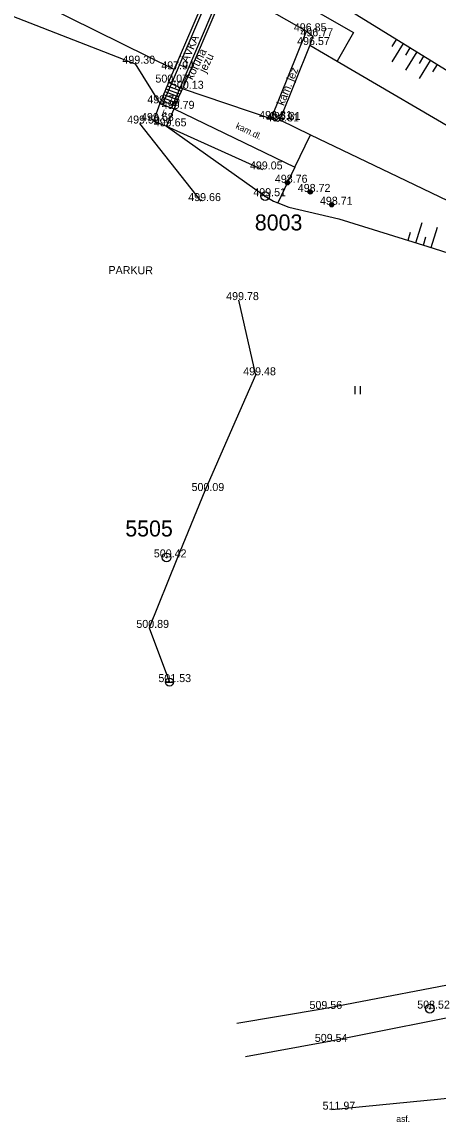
# Model space of a CAD drawing. Extents: x -668867 to -667827, y -1131943 to -1131019.
# Drawn here: x -668314 to -668275, y -1131724 to -1131620.9 of the extents above; entities that cross this region are included whole.
import ezdxf

# ---------------------------------------------------------------- set-up
doc = ezdxf.new("R2010")
doc.units = 0
for name, color, linetype in [('G_Bod_tecka', 7, 'Continuous'), ('G_Bod_vyska', 7, 'Continuous'), ('G_Bodove_pole', 7, 'Continuous'), ('G_Breh_Teren', 7, 'Continuous'), ('G_Budovy_Objekty', 7, 'Continuous'), ('G_Cesty_Schody', 7, 'Continuous'), ('G_Objekty-Studny', 7, 'Continuous'), ('G_Plochy_zpevnene', 7, 'Continuous'), ('G_Ploty', 7, 'Continuous'), ('G_Popisy_povrchu', 7, 'Continuous'), ('G_Poznamky_odkaz', 7, 'Continuous'), ('G_Site-Sloupy', 7, 'Continuous'), ('G_Vyskove_srafy', 7, 'Continuous'), ('G_Zabradli_Svodidla', 7, 'Continuous'), ('G_Zelen-okraj', 7, 'Continuous'), ('G_Zelen-rozhrani', 7, 'Continuous'), ('G_Zelen-Znacky', 7, 'Continuous')]:
    doc.layers.add(name, color=color, linetype=linetype)

msp = doc.modelspace()

# ---------------------------------------------------------------- linework, layer by layer
at = {"layer": 'G_Bod_tecka'}
for p, q in [((-668287.32, -1131621.79), (-668287.32, -1131621.79)), ((-668286.71, -1131622.26), (-668286.71, -1131622.26)), ((-668287.01, -1131623.08), (-668287.01, -1131623.08)), ((-668303.4, -1131624.83), (-668303.4, -1131624.83)), ((-668299.77, -1131625.36), (-668299.77, -1131625.36)), ((-668300.26, -1131626.6), (-668300.26, -1131626.6)), ((-668298.96, -1131627.18), (-668298.96, -1131627.18)), ((-668301.07, -1131628.55), (-668301.07, -1131628.55)), ((-668299.72, -1131629.06), (-668299.72, -1131629.06)), ((-668302.98, -1131630.44), (-668302.98, -1131630.44)), ((-668301.67, -1131630.2), (-668301.67, -1131630.2)), ((-668290.63, -1131630.01), (-668290.63, -1131630.01)), ((-668289.96, -1131630.24), (-668289.96, -1131630.24)), ((-668289.82, -1131630.1), (-668289.82, -1131630.1)), ((-668300.46, -1131630.7), (-668300.46, -1131630.7)), ((-668291.43, -1131634.74), (-668291.43, -1131634.74)), ((-668289.1, -1131635.99), (-668289.1, -1131635.99)), ((-668286.96, -1131636.85), (-668286.96, -1131636.85)), ((-668297.22, -1131637.71), (-668297.22, -1131637.71)), ((-668291.19, -1131637.25), (-668291.19, -1131637.25)), ((-668284.95, -1131638.05), (-668284.95, -1131638.05)), ((-668293.68, -1131646.99), (-668293.68, -1131646.99)), ((-668292.09, -1131654.04), (-668292.09, -1131654.04)), ((-668296.87, -1131664.89), (-668296.87, -1131664.89)), ((-668300.44, -1131671.11), (-668300.44, -1131671.11)), ((-668302.07, -1131677.72), (-668302.07, -1131677.72)), ((-668300.17, -1131682.8), (-668300.17, -1131682.8)), ((-668285.83, -1131713.44), (-668285.83, -1131713.44)), ((-668275.73, -1131713.41), (-668275.73, -1131713.41)), ((-668285.34, -1131716.53), (-668285.34, -1131716.53)), ((-668284.92, -1131722.88), (-668284.92, -1131722.88))]:
    msp.add_line(p, q, dxfattribs=at)
at = {"layer": 'G_Bodove_pole'}
for centre, radius in [((-668291.19, -1131637.25), 0.412), ((-668291.19, -1131637.25), 0.05), ((-668300.44, -1131671.11), 0.412), ((-668300.44, -1131671.11), 0.05), ((-668275.73, -1131713.41), 0.412), ((-668275.73, -1131713.41), 0.05)]:
    msp.add_circle(centre, radius, dxfattribs=at)
at = {"layer": 'G_Breh_Teren'}
for p, q in [((-668287.01, -1131623.08), (-668284.42, -1131624.59)), ((-668289.82, -1131630.1), (-668286.92, -1131631.49))]:
    msp.add_line(p, q, dxfattribs=at)
for points in [[(-668415.19, -1131594.85), (-668405.92, -1131594.75), (-668396.65, -1131594.66), (-668394.42, -1131594.69), (-668390.28, -1131595.04), (-668386.68, -1131595.6), (-668383.55, -1131596.28), (-668378.11, -1131597.76), (-668370.03, -1131600.44), (-668362.02, -1131603.26), (-668343.64, -1131609.6), (-668334.51, -1131612.86), (-668325.43, -1131616.28), (-668314.41, -1131620.56), (-668303.4, -1131624.83)], [(-668299.73, -1131625.37), (-668311.95, -1131619.35)], [(-668303.4, -1131624.83), (-668301.07, -1131628.55)], [(-668284.42, -1131624.59), (-668271.7, -1131632.04), (-668256.39, -1131640.99), (-668252.24, -1131643.3), (-668248.54, -1131645.17), (-668241.94, -1131648.18), (-668231.8, -1131652.31), (-668221.46, -1131656.34), (-668218.75, -1131657.34), (-668213.93, -1131658.81), (-668210.27, -1131659.7), (-668204.78, -1131660.72)], [(-668300.46, -1131630.7), (-668295.83, -1131633.98), (-668291.19, -1131637.25), (-668290.42, -1131637.71), (-668290.01, -1131637.87)], [(-668286.92, -1131631.49), (-668277.98, -1131635.78), (-668266.14, -1131641.46), (-668254.29, -1131647.41), (-668242.42, -1131653.43), (-668237.46, -1131655.76), (-668233.04, -1131657.64), (-668229.12, -1131659.17), (-668222.17, -1131661.58), (-668216.91, -1131663.18), (-668208.97, -1131665.24), (-668201.03, -1131666.92), (-668199.36, -1131667.09), (-668198.09, -1131667.04), (-668196.17, -1131666.72), (-668194.32, -1131666.1)], [(-668290.01, -1131637.87), (-668288.96, -1131638.28), (-668284.28, -1131639.36), (-668275.91, -1131641.96), (-668267.55, -1131644.62), (-668264.11, -1131645.93), (-668261.21, -1131647.32), (-668258.74, -1131648.68), (-668254.51, -1131651.29), (-668248.2, -1131655.36), (-668244.98, -1131657.3), (-668241.67, -1131659.07), (-668236.54, -1131661.51), (-668231.93, -1131663.55), (-668227.82, -1131665.21), (-668224.18, -1131666.55), (-668220.99, -1131667.61), (-668218.18, -1131668.43), (-668213.27, -1131669.62), (-668209.61, -1131670.26), (-668206.88, -1131670.59)], [(-668302.07, -1131677.72), (-668300.17, -1131682.8)]]:
    msp.add_lwpolyline(points, dxfattribs=at)
at = {"layer": 'G_Budovy_Objekty'}
for p, q in [((-668297.96, -1131621.25), (-668296.1, -1131616.94)), ((-668294.81, -1131617.51), (-668298.96, -1131627.18)), ((-668299.73, -1131625.37), (-668297.96, -1131621.25)), ((-668300.26, -1131626.6), (-668299.73, -1131625.37))]:
    msp.add_line(p, q, dxfattribs=at)
at = {"layer": 'G_Cesty_Schody'}
for p, q in [((-668287.32, -1131621.79), (-668286.71, -1131622.26)), ((-668286.71, -1131622.26), (-668287.01, -1131623.08)), ((-668289.96, -1131630.24), (-668290.63, -1131630.01)), ((-668289.82, -1131630.1), (-668289.96, -1131630.24))]:
    msp.add_line(p, q, dxfattribs=at)
for points in [[(-668300.61, -1131627.44), (-668300.73, -1131627.72)], [(-668300.5, -1131627.17), (-668300.61, -1131627.44)], [(-668300.61, -1131627.44), (-668299.28, -1131627.95)], [(-668300.38, -1131626.89), (-668300.5, -1131627.17)], [(-668300.5, -1131627.17), (-668299.16, -1131627.67)], [(-668300.26, -1131626.6), (-668300.38, -1131626.89)], [(-668300.38, -1131626.89), (-668299.05, -1131627.39)], [(-668298.96, -1131627.18), (-668300.26, -1131626.6)], [(-668299.16, -1131627.67), (-668299.05, -1131627.39)], [(-668299.05, -1131627.39), (-668298.96, -1131627.18)], [(-668300.96, -1131628.28), (-668301.07, -1131628.55)], [(-668301.07, -1131628.55), (-668299.72, -1131629.06)], [(-668300.84, -1131628), (-668300.96, -1131628.28)], [(-668300.96, -1131628.28), (-668299.61, -1131628.79)], [(-668300.73, -1131627.72), (-668300.84, -1131628)], [(-668300.84, -1131628), (-668299.5, -1131628.51)], [(-668300.73, -1131627.72), (-668299.39, -1131628.23)], [(-668299.61, -1131628.79), (-668299.5, -1131628.51)], [(-668299.5, -1131628.51), (-668299.39, -1131628.23)], [(-668299.39, -1131628.23), (-668299.28, -1131627.95)], [(-668299.28, -1131627.95), (-668299.16, -1131627.67)], [(-668299.72, -1131629.06), (-668299.61, -1131628.79)], [(-668293.86, -1131714.78), (-668285.83, -1131713.44), (-668270.48, -1131710.49), (-668262.65, -1131708.7), (-668254.82, -1131706.91), (-668251.21, -1131706.13), (-668245.77, -1131705.05), (-668240.35, -1131703.91), (-668234.27, -1131702.51), (-668228.2, -1131701.07), (-668225.41, -1131700.4), (-668222.63, -1131699.73), (-668217.07, -1131698.35), (-668211.52, -1131696.94), (-668207.58, -1131695.86)], [(-668206.76, -1131698.82), (-668210.49, -1131699.81), (-668219.14, -1131701.98), (-668227.81, -1131704.09), (-668233.92, -1131705.54), (-668240.04, -1131706.94), (-668247.27, -1131708.53), (-668254.5, -1131710.1), (-668261.74, -1131711.65), (-668268.98, -1131713.22), (-668269.64, -1131713.37), (-668270.29, -1131713.51), (-668285.34, -1131716.53), (-668293.02, -1131717.92)]]:
    msp.add_lwpolyline(points, dxfattribs=at)
at = {"layer": 'G_Objekty-Studny'}
msp.add_lwpolyline([(-668300.55, -1131682.8), (-668299.8, -1131682.8)], dxfattribs=at)
msp.add_circle((-668300.17, -1131682.8), 0.375, dxfattribs=at)
at = {"layer": 'G_Plochy_zpevnene'}
for points in [[(-668293.97, -1131615.57), (-668282.89, -1131621.91)], [(-668294.81, -1131617.51), (-668287.32, -1131621.79)], [(-668290.63, -1131630.01), (-668287.32, -1131621.79)], [(-668282.89, -1131621.91), (-668284.42, -1131624.59)], [(-668287.01, -1131623.08), (-668289.82, -1131630.1)], [(-668290.63, -1131630.01), (-668298.96, -1131627.18)], [(-668301.07, -1131628.55), (-668301.67, -1131630.2)], [(-668300.46, -1131630.7), (-668299.72, -1131629.06)], [(-668299.72, -1131629.06), (-668288.4, -1131634.54)], [(-668301.67, -1131630.2), (-668300.46, -1131630.7)], [(-668288.4, -1131634.54), (-668286.92, -1131631.49)], [(-668284.92, -1131722.88), (-668270.22, -1131721.43), (-668270.12, -1131721.42)]]:
    msp.add_lwpolyline(points, dxfattribs=at)
at = {"layer": 'G_Ploty'}
for p, q in [((-668264.03, -1131631.7), (-668292.33, -1131614.27)), ((-668302.98, -1131630.44), (-668297.22, -1131637.71)), ((-668293.68, -1131646.99), (-668292.09, -1131654.04))]:
    msp.add_line(p, q, dxfattribs=at)
at = {"layer": 'G_Site-Sloupy'}
for centre, radius in [((-668289.1, -1131635.99), 0.2), ((-668289.1, -1131635.99), 0.18), ((-668289.1, -1131635.99), 0.16), ((-668289.1, -1131635.99), 0.14), ((-668289.1, -1131635.99), 0.12), ((-668289.1, -1131635.99), 0.1), ((-668289.1, -1131635.99), 0.08), ((-668289.1, -1131635.99), 0.06), ((-668289.1, -1131635.99), 0.04), ((-668289.1, -1131635.99), 0.02), ((-668286.96, -1131636.85), 0.2), ((-668286.96, -1131636.85), 0.18), ((-668286.96, -1131636.85), 0.16), ((-668286.96, -1131636.85), 0.14), ((-668286.96, -1131636.85), 0.12), ((-668286.96, -1131636.85), 0.1), ((-668286.96, -1131636.85), 0.08), ((-668286.96, -1131636.85), 0.06), ((-668286.96, -1131636.85), 0.04), ((-668286.96, -1131636.85), 0.02), ((-668284.95, -1131638.05), 0.2), ((-668284.95, -1131638.05), 0.18), ((-668284.95, -1131638.05), 0.16), ((-668284.95, -1131638.05), 0.14), ((-668284.95, -1131638.05), 0.12), ((-668284.95, -1131638.05), 0.1), ((-668284.95, -1131638.05), 0.08), ((-668284.95, -1131638.05), 0.06), ((-668284.95, -1131638.05), 0.04), ((-668284.95, -1131638.05), 0.02)]:
    msp.add_circle(centre, radius, dxfattribs=at)
at = {"layer": 'G_Vyskove_srafy'}
for points in [[(-668278.88, -1131622.55), (-668279.3, -1131623.23)], [(-668278.24, -1131622.94), (-668279.29, -1131624.65)], [(-668277.6, -1131623.34), (-668278.02, -1131624.02)], [(-668276.96, -1131623.73), (-668278.01, -1131625.44)], [(-668276.33, -1131624.12), (-668276.75, -1131624.81)], [(-668275.69, -1131624.52), (-668276.74, -1131626.22)], [(-668275.05, -1131624.91), (-668275.47, -1131625.59)], [(-668277.06, -1131641.61), (-668276.46, -1131639.7)], [(-668277.77, -1131641.38), (-668277.54, -1131640.62)], [(-668275.62, -1131642.06), (-668275.02, -1131640.15)], [(-668276.34, -1131641.83), (-668276.1, -1131641.07)]]:
    msp.add_lwpolyline(points, dxfattribs=at)
at = {"layer": 'G_Zabradli_Svodidla'}
for p, q in [((-668295.02, -1131615.08), (-668300.82, -1131628.65)), ((-668294.22, -1131615.45), (-668299.99, -1131628.96)), ((-668300.46, -1131630.7), (-668291.43, -1131634.74))]:
    msp.add_line(p, q, dxfattribs=at)
at = {"layer": 'G_Zelen-okraj'}
msp.add_lwpolyline([(-668288.4, -1131634.54), (-668290.01, -1131637.87)], dxfattribs=at)
at = {"layer": 'G_Zelen-rozhrani'}
msp.add_lwpolyline([(-668292.09, -1131654.04), (-668294.49, -1131659.44), (-668296.85, -1131664.86), (-668299.48, -1131671.28), (-668302.07, -1131677.72)], dxfattribs=at)
at = {"layer": 'G_Zelen-Znacky'}
for p, q in [((-668282.75, -1131655.81), (-668282.75, -1131655.06)), ((-668282.25, -1131655.81), (-668282.25, -1131655.06))]:
    msp.add_line(p, q, dxfattribs=at)

# ---------------------------------------------------------------- texts
at = {"layer": 'G_Bod_vyska'}
for s, p in [('496.85', (-668288.5, -1131621.79)), ('496.57', (-668288.19, -1131623.08)), ('496.77', (-668287.88, -1131622.26)), ('499.30', (-668304.59, -1131624.83)), ('497.94', (-668300.94, -1131625.36)), ('500.07', (-668301.49, -1131626.6)), ('500.13', (-668300.03, -1131627.18)), ('499.76', (-668302.25, -1131628.55)), ('499.79', (-668300.89, -1131629.06)), ('499.68', (-668302.84, -1131630.2)), ('496.81', (-668291.75, -1131630.01)), ('496.81', (-668291.08, -1131630.24)), ('496.31', (-668290.94, -1131630.1)), ('499.59', (-668304.14, -1131630.44)), ('499.65', (-668301.64, -1131630.7)), ('499.05', (-668292.62, -1131634.74)), ('498.76', (-668290.28, -1131635.99)), ('499.51', (-668292.3, -1131637.25)), ('498.72', (-668288.13, -1131636.85)), ('499.66', (-668298.41, -1131637.71)), ('498.71', (-668286.05, -1131638.05)), ('499.78', (-668294.85, -1131646.99)), ('499.48', (-668293.25, -1131654.04)), ('500.09', (-668298.1, -1131664.89)), ('500.42', (-668301.64, -1131671.11)), ('500.89', (-668303.28, -1131677.72)), ('501.53', (-668301.21, -1131682.8)), ('509.56', (-668287.03, -1131713.44)), ('508.52', (-668276.92, -1131713.41)), ('509.54', (-668286.53, -1131716.53)), ('511.97', (-668285.8, -1131722.88))]:
    msp.add_text(s, height=0.75, dxfattribs=at).set_placement(p)
at = {"layer": 'G_Bodove_pole'}
for s, p in [('8003', (-668292.16, -1131640.46)), ('5505', (-668304.32, -1131669.15))]:
    msp.add_text(s, height=1.5, dxfattribs=at).set_placement(p)
at = {"layer": 'G_Popisy_povrchu'}
for s, rotation, p in [('b.', 339.2111, (-668300.97, -1131629.7)), ('kam.dl.', 334.1994, (-668294.01, -1131630.86))]:
    msp.add_text(s, height=0.6, rotation=rotation, dxfattribs=at).set_placement(p)
msp.add_text('asf.', height=0.6, dxfattribs=at).set_placement((-668278.88, -1131724.03))
at = {"layer": 'G_Poznamky_odkaz'}
for s, rotation, p in [('LÁVKA', 66.5029, (-668298.67, -1131625.32)), ('koruna', 63.9527, (-668298.01, -1131626.4)), ('jezu', 63.9527, (-668296.79, -1131625.74)), ('kam. jez', 68.2619, (-668289.44, -1131628.82)), ('PARKUR', 359.5235, (-668305.9, -1131644.54))]:
    msp.add_text(s, height=0.75, rotation=rotation, dxfattribs=at).set_placement(p)

doc.saveas('drawing.dxf')
